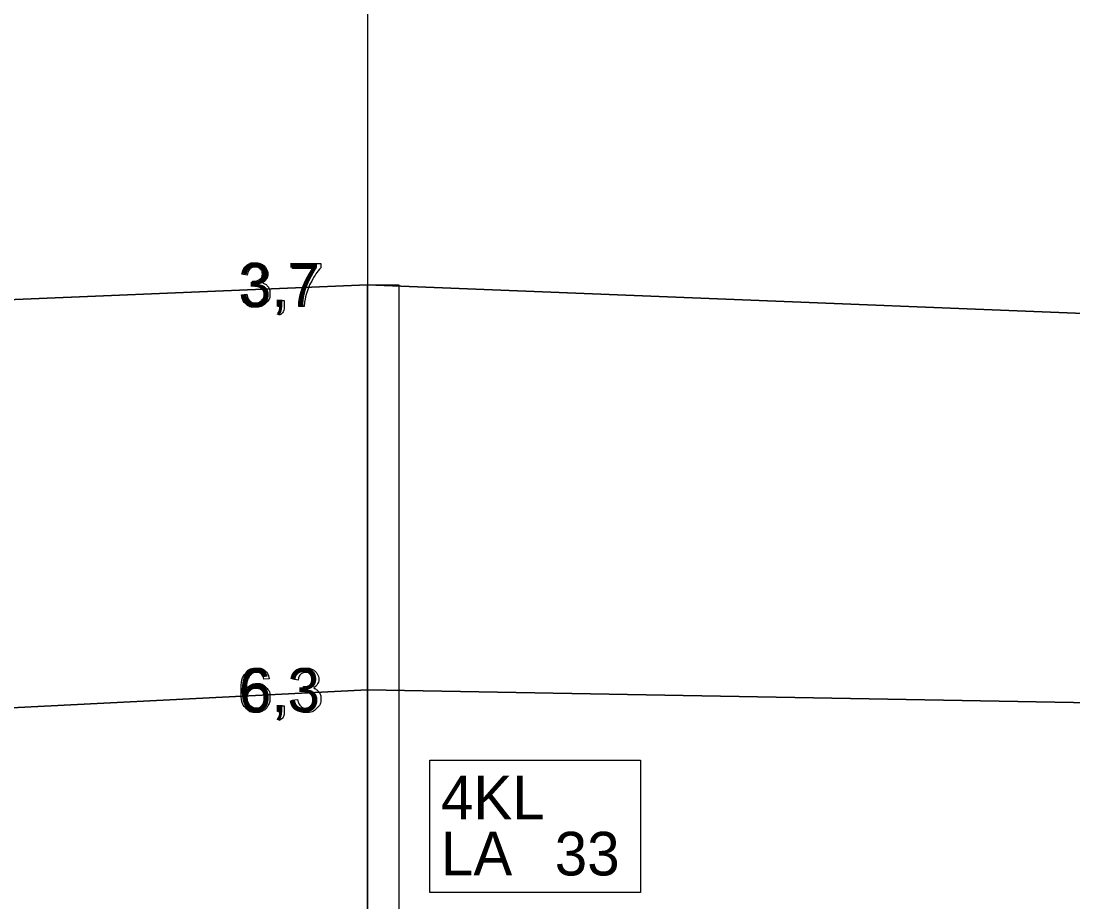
# Model space of a CAD drawing. Extents: x 532503 to 539665, y 6557663 to 6561526.
# Drawn here: x 538112.9 to 538247.8, y 6560367.9 to 6560480.9 of the extents above; entities that cross this region are included whole.
import ezdxf

# ---------------------------------------------------------------- set-up
doc = ezdxf.new("R2010")
doc.units = 0
for name, color, linetype in [('Default', 7, 'Continuous'), ('GEOLPUNKT', 7, 'Continuous'), ('Plokid', 7, 'Continuous'), ('Proovid', 7, 'Continuous'), ('Täide', 7, 'Continuous')]:
    doc.layers.add(name, color=color, linetype=linetype)

msp = doc.modelspace()

# ---------------------------------------------------------------- linework, layer by layer
at = {"layer": 'Default'}
for points in [[(537114.82, 6560272.67), (537235.3, 6560321.87), (537242.05, 6560326.27), (537267.99, 6560346.27), (537409.98, 6560463.67), (537409.98, 6560463.67), (537409.98, 6560463.67), (537680.4, 6560479.07), (537680.4, 6560479.07), (537927.28, 6560437.47), (537927.28, 6560437.47), (538157.31, 6560447.07), (538157.31, 6560447.07), (538426.58, 6560436.27), (538426.58, 6560436.27), (538556.7, 6560436.87), (538556.7, 6560436.87), (538783.9, 6560390.27), (538783.9, 6560390.27)], [(537409.98, 6560463.67), (537409.98, 6560463.67), (537680.4, 6560479.07), (537680.4, 6560479.07), (537927.28, 6560437.47), (537927.28, 6560437.47), (538157.31, 6560447.07), (538157.31, 6560447.07), (538426.58, 6560436.27), (538426.58, 6560436.27), (538556.7, 6560436.87), (538556.7, 6560436.87), (538783.9, 6560390.27), (538809.14, 6560385.09)], [(537327.58, 6560397.59), (537409.98, 6560401.67), (537680.4, 6560415.07), (537927.28, 6560383.47), (538157.31, 6560395.07), (538426.58, 6560390.27), (538556.7, 6560374.87), (538783.9, 6560390.27), (538809.14, 6560385.09)]]:
    msp.add_lwpolyline(points, dxfattribs=at)
at = {"layer": 'GEOLPUNKT'}
msp.add_line((538157.31, 6560521.07), (538157.31, 6560221.07), dxfattribs=at)
at = {"layer": 'Plokid'}
msp.add_lwpolyline([(537119.21, 6560274.46), (537235.3, 6560321.87), (537242.05, 6560326.27), (537267.99, 6560346.27), (537291.08, 6560365.36), (537409.98, 6560463.67), (537409.98, 6560463.67), (537680.4, 6560479.07), (537680.4, 6560479.07), (537927.28, 6560437.47), (537927.28, 6560437.47), (538157.31, 6560447.07), (538157.31, 6560447.07), (538426.58, 6560436.27), (538426.58, 6560436.27), (538556.7, 6560436.87), (538556.7, 6560436.87), (538783.9, 6560390.27), (538783.9, 6560390.27)], dxfattribs=at)
at = {"layer": 'Proovid'}
for points in [[(538147.69, 6560449.14), (538147.69, 6560449.8), (538151.31, 6560449.8), (538151.31, 6560449.26)], [(538150.43, 6560449.14), (538147.69, 6560449.14)], [(538141.88, 6560448.32), (538141.19, 6560448.44)], [(538142.48, 6560446.93), (538142.55, 6560447.53)], [(538141.12, 6560445.76), (538141.81, 6560445.85)], [(538145.84, 6560444.27), (538145.84, 6560445.05), (538146.62, 6560445.05), (538146.62, 6560444.27)], [(538146.23, 6560444.27), (538145.84, 6560444.27)], [(538149.18, 6560444.27), (538148.47, 6560444.27)], [(538145.98, 6560443.16), (538145.79, 6560443.45)], [(538144.69, 6560396.5), (538144.01, 6560396.44)], [(538148.4, 6560396.32), (538147.71, 6560396.44)], [(538149, 6560394.93), (538149.07, 6560395.53)], [(538147.64, 6560393.76), (538148.33, 6560393.85)], [(538145.84, 6560392.27), (538145.84, 6560393.05), (538146.62, 6560393.05), (538146.62, 6560392.27)], [(538145.98, 6560391.16), (538145.79, 6560391.45)], [(538146.23, 6560392.27), (538145.84, 6560392.27)]]:
    msp.add_lwpolyline(points, dxfattribs=at)
for points in [[(538157.31, 6560447.07), (538161.31, 6560447.07), (538161.31, 6560301.07), (538157.31, 6560301.07)], [(538165.31, 6560386.07), (538192.31, 6560386.07), (538192.31, 6560369.07), (538165.31, 6560369.07)]]:
    msp.add_lwpolyline(points, close=True, dxfattribs=at)
for points in [[(538141.19, 6560448.44), (538141.32, 6560449.13), (538141.76, 6560449.51), (538142.21, 6560449.89), (538142.87, 6560449.89), (538143.33, 6560449.89), (538143.72, 6560449.7), (538144.11, 6560449.5), (538144.31, 6560449.16), (538144.51, 6560448.82), (538144.51, 6560448.44), (538144.51, 6560448.08), (538144.32, 6560447.78), (538144.12, 6560447.48), (538143.74, 6560447.31), (538144.24, 6560447.19), (538144.51, 6560446.83), (538144.79, 6560446.47), (538144.79, 6560445.93), (538144.79, 6560445.2), (538144.25, 6560444.69), (538143.72, 6560444.18), (538142.9, 6560444.18), (538142.16, 6560444.18), (538141.68, 6560444.62), (538141.19, 6560445.06), (538141.12, 6560445.76)], [(538142.55, 6560447.53), (538142.62, 6560447.52), (538142.66, 6560447.52), (538143.1, 6560447.52), (538143.45, 6560447.75), (538143.81, 6560447.98), (538143.81, 6560448.45), (538143.81, 6560448.83), (538143.55, 6560449.08), (538143.29, 6560449.33), (538142.89, 6560449.33), (538142.49, 6560449.33), (538142.22, 6560449.08), (538141.95, 6560448.82), (538141.88, 6560448.32)], [(538148.47, 6560444.27), (538148.48, 6560444.93), (538148.73, 6560445.87), (538148.97, 6560446.8), (538149.44, 6560447.67), (538149.9, 6560448.54), (538150.43, 6560449.14)], [(538151.31, 6560449.26), (538150.77, 6560448.69), (538150.25, 6560447.75), (538149.73, 6560446.81), (538149.44, 6560445.81), (538149.23, 6560445.11), (538149.18, 6560444.27)], [(538141.81, 6560445.85), (538141.93, 6560445.26), (538142.21, 6560445), (538142.49, 6560444.74), (538142.9, 6560444.74), (538143.39, 6560444.74), (538143.72, 6560445.08), (538144.06, 6560445.42), (538144.06, 6560445.91), (538144.06, 6560446.39), (538143.75, 6560446.69), (538143.44, 6560447), (538142.96, 6560447), (538142.77, 6560447), (538142.48, 6560446.93)], [(538145.79, 6560443.45), (538146.01, 6560443.55), (538146.11, 6560443.74), (538146.21, 6560443.92), (538146.23, 6560444.27)], [(538146.62, 6560444.27), (538146.62, 6560443.84), (538146.47, 6560443.57), (538146.31, 6560443.31), (538145.98, 6560443.16)], [(538144.01, 6560396.44), (538143.91, 6560396.85), (538143.75, 6560397.03), (538143.47, 6560397.33), (538143.06, 6560397.33), (538142.73, 6560397.33), (538142.48, 6560397.14), (538142.15, 6560396.91), (538141.97, 6560396.45), (538141.78, 6560396), (538141.77, 6560395.16), (538142.02, 6560395.54), (538142.38, 6560395.72), (538142.74, 6560395.9), (538143.13, 6560395.9), (538143.82, 6560395.9), (538144.3, 6560395.4), (538144.79, 6560394.89), (538144.79, 6560394.09), (538144.79, 6560393.56), (538144.56, 6560393.11), (538144.33, 6560392.66), (538143.93, 6560392.42), (538143.54, 6560392.18), (538143.03, 6560392.18), (538142.17, 6560392.18), (538141.63, 6560392.81), (538141.09, 6560393.44), (538141.09, 6560394.89), (538141.09, 6560396.51), (538141.69, 6560397.25), (538142.21, 6560397.89), (538143.1, 6560397.89), (538143.76, 6560397.89), (538144.18, 6560397.52), (538144.61, 6560397.15), (538144.69, 6560396.5)], [(538147.71, 6560396.44), (538147.84, 6560397.13), (538148.28, 6560397.51), (538148.73, 6560397.89), (538149.4, 6560397.89), (538149.86, 6560397.89), (538150.24, 6560397.7), (538150.63, 6560397.5), (538150.83, 6560397.16), (538151.04, 6560396.82), (538151.04, 6560396.44), (538151.04, 6560396.08), (538150.84, 6560395.78), (538150.65, 6560395.48), (538150.26, 6560395.31), (538150.76, 6560395.19), (538151.04, 6560394.83), (538151.31, 6560394.47), (538151.31, 6560393.93), (538151.31, 6560393.2), (538150.77, 6560392.69), (538150.24, 6560392.18), (538149.42, 6560392.18), (538148.69, 6560392.18), (538148.2, 6560392.62), (538147.71, 6560393.06), (538147.64, 6560393.76)], [(538149.07, 6560395.53), (538149.14, 6560395.52), (538149.19, 6560395.52), (538149.62, 6560395.52), (538149.98, 6560395.75), (538150.33, 6560395.98), (538150.33, 6560396.45), (538150.33, 6560396.83), (538150.07, 6560397.08), (538149.82, 6560397.33), (538149.41, 6560397.33), (538149.01, 6560397.33), (538148.74, 6560397.08), (538148.47, 6560396.82), (538148.4, 6560396.32)], [(538141.88, 6560394.08), (538141.88, 6560393.73), (538142.03, 6560393.4), (538142.18, 6560393.08), (538142.45, 6560392.91), (538142.72, 6560392.74), (538143.02, 6560392.74), (538143.46, 6560392.74), (538143.77, 6560393.09), (538144.08, 6560393.44), (538144.08, 6560394.05), (538144.08, 6560394.63), (538143.77, 6560394.96), (538143.46, 6560395.3), (538142.99, 6560395.3), (538142.53, 6560395.3), (538142.2, 6560394.96), (538141.88, 6560394.63), (538141.88, 6560394.08)], [(538148.33, 6560393.85), (538148.45, 6560393.26), (538148.73, 6560393), (538149.02, 6560392.74), (538149.43, 6560392.74), (538149.91, 6560392.74), (538150.25, 6560393.08), (538150.58, 6560393.42), (538150.58, 6560393.91), (538150.58, 6560394.39), (538150.27, 6560394.69), (538149.96, 6560395), (538149.48, 6560395), (538149.29, 6560395), (538149, 6560394.93)], [(538145.79, 6560391.45), (538146.01, 6560391.55), (538146.11, 6560391.74), (538146.21, 6560391.92), (538146.23, 6560392.27)], [(538146.62, 6560392.27), (538146.62, 6560391.84), (538146.47, 6560391.57), (538146.31, 6560391.31), (538145.98, 6560391.16)]]:
    msp.add_open_spline(points, degree=3, dxfattribs=at)
at = {"layer": 'Täide'}
for p, q in [((537927.28, 6560437.47), (538157.31, 6560447.07)), ((538157.31, 6560447.07), (538426.58, 6560436.27))]:
    msp.add_line(p, q, dxfattribs=at)
for points in [[(538783.9, 6560390.27), (538783.9, 6560390.27), (538556.7, 6560436.87), (538426.58, 6560436.27), (538157.31, 6560447.07), (537927.28, 6560437.47), (537680.4, 6560479.07), (537409.98, 6560463.67), (537387.62, 6560462.4)], [(538809.14, 6560385.09), (538783.9, 6560390.27), (538556.7, 6560436.87), (538426.58, 6560436.27), (538157.31, 6560447.07), (537927.28, 6560437.47), (537680.4, 6560479.07), (537409.98, 6560463.67), (537409.98, 6560463.67)], [(537327.58, 6560397.59), (537409.98, 6560401.67), (537680.4, 6560415.07), (537927.28, 6560383.47), (538157.31, 6560395.07), (538426.58, 6560390.27), (538556.7, 6560374.87), (538556.7, 6560374.87), (538556.7, 6560374.87)], [(538783.9, 6560390.27), (538556.7, 6560374.87), (538426.58, 6560390.27), (538157.31, 6560395.07), (537927.28, 6560383.47), (537680.4, 6560415.07)]]:
    msp.add_lwpolyline(points, dxfattribs=at)

# ---------------------------------------------------------------- texts
at = {"layer": 'Proovid'}
for s, p in [('3,7', (538140.79, 6560444.27)), ('6,3', (538140.79, 6560392.27)), ('4KL', (538166.71, 6560378.47)), ('LA', (538166.71, 6560371.27)), ('33', (538181.31, 6560371.27))]:
    msp.add_text(s, height=5.6, dxfattribs=at).set_placement(p)

doc.saveas('drawing.dxf')
